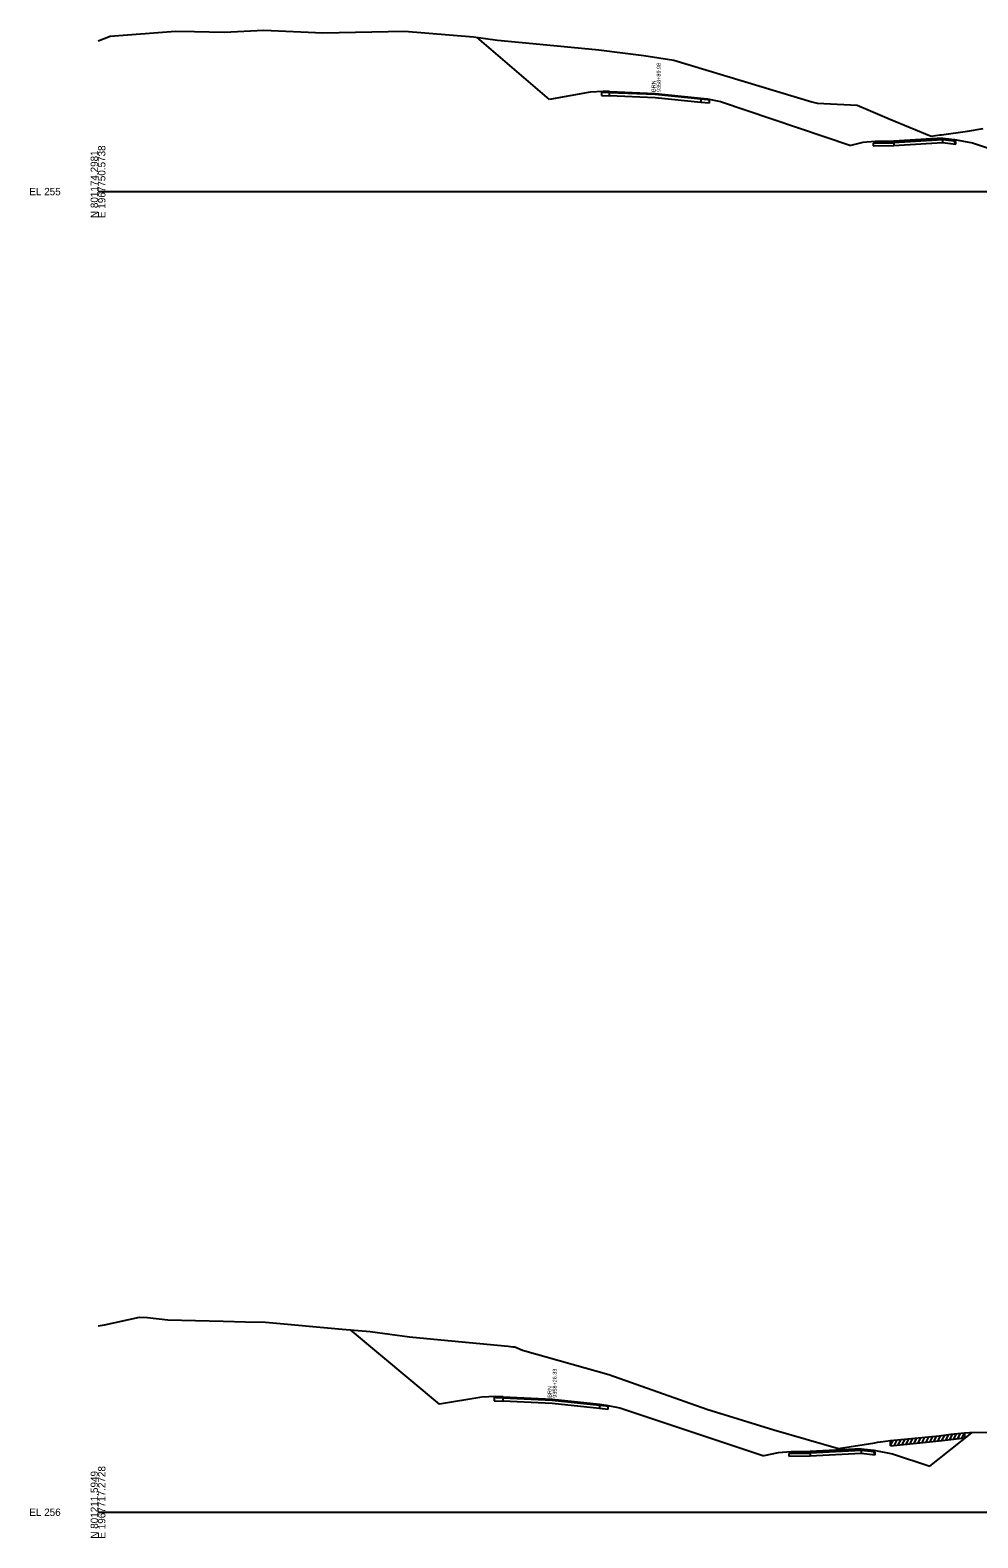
# Model space of a CAD drawing. Extents: x 1017 to 19997, y -1947 to 50737.
# Drawn here: x 13974 to 14333, y 2490 to 3061 of the extents above; entities that cross this region are included whole.
import ezdxf

# ---------------------------------------------------------------- set-up
doc = ezdxf.new("R2010")
doc.units = 0
for name, color, linetype in [('RD_GPK_XS_Cell', 7, 'Continuous'), ('RD_XS_Base', 7, 'Continuous'), ('RD_XS_ExGround', 7, 'Continuous'), ('RD_XS_ExPaveRet', 7, 'Continuous'), ('RD_XS_Greenside', 7, 'Continuous'), ('RD_XS_Pave', 7, 'Continuous'), ('RD_XS_PaveOvlay', 7, 'Continuous'), ('RD_XS_TieSlope', 7, 'Continuous'), ('RD_XS_TX_Notes', 7, 'Continuous')]:
    doc.layers.add(name, color=color, linetype=linetype)

msp = doc.modelspace()

# ---------------------------------------------------------------- linework, layer by layer
at = {"layer": 'RD_GPK_XS_Cell'}
for p, q in [((14000, 3000), (14600, 3000)), ((14000, 2500), (14600, 2500))]:
    msp.add_line(p, q, dxfattribs=at)
at = {"layer": 'RD_XS_Base'}
for points in [[(14190.63, 3037.66), (14190.63, 3036.33)], [(14193.71, 3037.54), (14190.63, 3037.66)], [(14193.71, 3037.54), (14211, 3036.85), (14228.28, 3035.07)], [(14193.71, 3036.2), (14193.71, 3037.54)], [(14190.63, 3036.33), (14193.71, 3036.2)], [(14228.28, 3033.76), (14211, 3035.51), (14193.71, 3036.2)], [(14228.28, 3035.07), (14228.28, 3033.76)], [(14228.28, 3035.07), (14230.75, 3034.82), (14231.37, 3034.76)], [(14231.37, 3033.42), (14228.28, 3033.76)], [(14231.37, 3034.76), (14231.37, 3033.42)], [(14319.66, 3019.63), (14319.66, 3018.63)], [(14324.82, 3018.01), (14324.25, 3019.08), (14319.66, 3019.63)], [(14324.82, 3019.01), (14324.25, 3019.08), (14319.66, 3019.63)], [(14301.3, 3018.44), (14294.27, 3018.32), (14293.44, 3018.3)], [(14293.44, 3018.3), (14293.44, 3017.3)], [(14293.44, 3017.3), (14301.3, 3017.44)], [(14301.3, 3017.44), (14319.66, 3018.63)], [(14301.3, 3018.44), (14301.3, 3017.44)], [(14319.66, 3018.63), (14324.82, 3018.01)], [(14324.82, 3018.01), (14324.82, 3019.01)], [(14150, 2543.52), (14150, 2542.19)], [(14153.33, 2543.36), (14150, 2543.52)], [(14150, 2542.19), (14153.33, 2542.02)], [(14153.33, 2543.36), (14171.9, 2542.47), (14189.82, 2540.54)], [(14153.33, 2542.02), (14153.33, 2543.36)], [(14189.82, 2539.23), (14171.9, 2541.13), (14153.33, 2542.02)], [(14189.82, 2540.54), (14189.82, 2539.23)], [(14189.82, 2540.54), (14192.38, 2540.27), (14193.03, 2540.2)], [(14193.03, 2540.2), (14193.03, 2538.87)], [(14193.03, 2538.87), (14189.82, 2539.23)], [(14288.97, 2523.41), (14288.97, 2522.41)], [(14294.27, 2521.76), (14293.68, 2522.84), (14288.97, 2523.41)], [(14294.27, 2522.76), (14293.68, 2522.84), (14288.97, 2523.41)], [(14269.65, 2522.35), (14262.37, 2522.28), (14261.52, 2522.27)], [(14261.52, 2522.27), (14261.52, 2521.27)], [(14261.52, 2521.27), (14269.65, 2521.35)], [(14269.65, 2521.35), (14288.97, 2522.41)], [(14269.65, 2522.35), (14269.65, 2521.35)], [(14288.97, 2522.41), (14294.27, 2521.76)], [(14294.27, 2521.76), (14294.27, 2522.76)]]:
    msp.add_lwpolyline(points, dxfattribs=at)
at = {"layer": 'RD_XS_ExGround'}
for points in [[(14000, 3057.03), (14004.57, 3058.82), (14029.3, 3060.76), (14036.48, 3060.64), (14047.73, 3060.33), (14062.72, 3061.12), (14085.15, 3060.1), (14116.05, 3060.71), (14142.13, 3058.58), (14151.25, 3057.36), (14169.89, 3055.58), (14189.65, 3053.69), (14198.53, 3052.49), (14206.66, 3051.47), (14217.95, 3049.7), (14270.25, 3033.97), (14272.29, 3033.46), (14287.44, 3032.69), (14291.61, 3030.91), (14299.48, 3027.61), (14315.49, 3020.99), (14318.76, 3021.45), (14319.29, 3021.54), (14329.19, 3022.91), (14335.08, 3023.84)], [(14000, 2570.62), (14002.4, 2570.96), (14015.71, 2573.92), (14018.68, 2573.77), (14026.37, 2572.88), (14047.44, 2572.4), (14055.86, 2572.15), (14063.37, 2571.97), (14092.48, 2569.27), (14102.98, 2568.41), (14117.96, 2566.41), (14129.85, 2565.28), (14155.3, 2562.85), (14157.04, 2562.65), (14157.8, 2562.61), (14160.71, 2561.32), (14193.39, 2552.12), (14230.56, 2539.08), (14255.88, 2531.26), (14280.33, 2524.15), (14294.16, 2526.34), (14295.13, 2526.49), (14296.29, 2526.7), (14300, 2527.2), (14318.5, 2528.99), (14322.94, 2529.5), (14328.08, 2530.12), (14329.96, 2530.13), (14342.19, 2530.3)]]:
    msp.add_lwpolyline(points, dxfattribs=at)
at = {"layer": 'RD_XS_ExPaveRet'}
for p, q in [((14315, 2526.65), (14316.05, 2528.75)), ((14316.5, 2526.79), (14317.55, 2528.9)), ((14318, 2526.94), (14319.06, 2529.05)), ((14319.5, 2527.1), (14320.56, 2529.22)), ((14321, 2527.28), (14322.06, 2529.4)), ((14322.5, 2527.45), (14323.56, 2529.57)), ((14324, 2527.63), (14325.07, 2529.76)), ((14325.5, 2527.81), (14326.57, 2529.94)), ((14327, 2527.99), (14328.07, 2530.12)), ((14328.08, 2530.12), (14328.08, 2528.12)), ((14300, 2525.2), (14301.05, 2527.3)), ((14300, 2525.2), (14300, 2527.2)), ((14300, 2525.2), (14318.5, 2526.99)), ((14301.5, 2525.34), (14302.55, 2527.44)), ((14303, 2525.49), (14304.05, 2527.59)), ((14304.5, 2525.63), (14305.55, 2527.73)), ((14306, 2525.78), (14307.05, 2527.88)), ((14307.5, 2525.92), (14308.55, 2528.03)), ((14309, 2526.07), (14310.05, 2528.17)), ((14310.5, 2526.21), (14311.55, 2528.32)), ((14312, 2526.36), (14313.05, 2528.46)), ((14313.5, 2526.5), (14314.55, 2528.61)), ((14318.5, 2526.99), (14322.94, 2527.5)), ((14322.94, 2527.5), (14328.08, 2528.12))]:
    msp.add_line(p, q, dxfattribs=at)
at = {"layer": 'RD_XS_Greenside'}
for points in [[(14186.29, 3037.68), (14170.93, 3034.83)], [(14191.24, 3037.96), (14186.29, 3037.68)], [(14230.75, 3035.14), (14235.69, 3034.15)], [(14235.69, 3034.15), (14284.96, 3017.5)], [(14324.25, 3019.71), (14331.13, 3018.42)], [(14289.55, 3018.56), (14284.96, 3017.5)], [(14294.27, 3018.95), (14289.55, 3018.56)], [(14331.13, 3018.42), (14344.9, 3013.75)], [(14145.33, 2543.59), (14129.34, 2540.89)], [(14150.66, 2543.81), (14145.33, 2543.59)], [(14192.38, 2540.59), (14197.51, 2539.57)], [(14197.51, 2539.57), (14252.04, 2521.36)], [(14293.68, 2523.47), (14300.75, 2522.13)], [(14257.51, 2522.55), (14252.04, 2521.36)], [(14262.37, 2522.92), (14257.51, 2522.55)], [(14300.75, 2522.13), (14314.9, 2517.39)]]:
    msp.add_lwpolyline(points, dxfattribs=at)
at = {"layer": 'RD_XS_Pave'}
for points in [[(14301.3, 3018.76), (14319.66, 3019.95)], [(14319.66, 3019.63), (14301.3, 3018.44)], [(14319.66, 3019.95), (14319.66, 3019.63)], [(14319.66, 3019.95), (14324.25, 3019.4)], [(14324.25, 3019.08), (14319.66, 3019.63)], [(14301.3, 3018.76), (14294.27, 3018.64)], [(14294.27, 3018.64), (14294.27, 3018.32)], [(14294.27, 3018.32), (14301.3, 3018.44)], [(14301.3, 3018.44), (14301.3, 3018.76)], [(14324.25, 3019.4), (14324.25, 3019.08)], [(14269.65, 2522.67), (14288.97, 2523.73)], [(14288.97, 2523.41), (14269.65, 2522.35)], [(14288.97, 2523.73), (14288.97, 2523.41)], [(14288.97, 2523.73), (14293.68, 2523.15)], [(14293.68, 2522.84), (14288.97, 2523.41)], [(14293.68, 2523.15), (14293.68, 2522.84)], [(14269.65, 2522.67), (14262.37, 2522.6)], [(14262.37, 2522.6), (14262.37, 2522.28)], [(14262.37, 2522.28), (14269.65, 2522.35)], [(14269.65, 2522.35), (14269.65, 2522.67)]]:
    msp.add_lwpolyline(points, dxfattribs=at)
at = {"layer": 'RD_XS_PaveOvlay'}
for points in [[(14191.24, 3037.96), (14191.24, 3037.64)], [(14193.71, 3037.85), (14191.24, 3037.96)], [(14191.24, 3037.64), (14193.71, 3037.54)], [(14193.71, 3037.85), (14211, 3037.16), (14228.28, 3035.39)], [(14193.71, 3037.54), (14193.71, 3037.85)], [(14228.28, 3035.39), (14228.28, 3035.07)], [(14228.28, 3035.39), (14230.75, 3035.14)], [(14230.75, 3034.82), (14228.28, 3035.07)], [(14230.75, 3035.14), (14230.75, 3034.82)], [(14319.66, 3020.26), (14301.3, 3019.07)], [(14319.66, 3019.95), (14319.66, 3020.26)], [(14319.66, 3020.26), (14324.25, 3019.71)], [(14324.25, 3019.71), (14324.25, 3019.4)], [(14301.3, 3019.07), (14294.27, 3018.95)], [(14294.27, 3018.95), (14294.27, 3018.64)], [(14301.3, 3019.07), (14301.3, 3018.76)], [(14150.66, 2543.81), (14150.66, 2543.49)], [(14153.33, 2543.67), (14150.66, 2543.81)], [(14150.66, 2543.49), (14153.33, 2543.36)], [(14153.33, 2543.67), (14171.9, 2542.78), (14189.82, 2540.86)], [(14153.33, 2543.36), (14153.33, 2543.67)], [(14189.82, 2540.86), (14189.82, 2540.54)], [(14189.82, 2540.86), (14192.38, 2540.59)], [(14192.38, 2540.27), (14189.82, 2540.54)], [(14192.38, 2540.59), (14192.38, 2540.27)], [(14288.97, 2524.05), (14269.65, 2522.99)], [(14288.97, 2523.73), (14288.97, 2524.05)], [(14288.97, 2524.05), (14293.68, 2523.47)], [(14293.68, 2523.47), (14293.68, 2523.15)], [(14269.65, 2522.99), (14262.37, 2522.92)], [(14262.37, 2522.92), (14262.37, 2522.6)], [(14269.65, 2522.99), (14269.65, 2522.67)]]:
    msp.add_lwpolyline(points, dxfattribs=at)
at = {"layer": 'RD_XS_TieSlope'}
for points in [[(14170.93, 3034.83), (14143.52, 3058.38)], [(14129.34, 2540.89), (14095.62, 2569.01)], [(14314.9, 2517.39), (14330.85, 2530.1)]]:
    msp.add_lwpolyline(points, dxfattribs=at)

# ---------------------------------------------------------------- texts
at = {"layer": 'RD_GPK_XS_Cell'}
for s, p in [('N 801174.2981', (14000, 2990)), ('E 1967750.5738', (14002.8, 2990)), ('E 1967717.2728', (14002.8, 2490)), ('N 801211.5949', (14000, 2490))]:
    msp.add_text(s, height=2.8, rotation=90, dxfattribs=at).set_placement(p)
for s, p in [('EL 255', (13974, 2998.6)), ('EL 256', (13974, 2498.6))]:
    msp.add_text(s, height=2.8, dxfattribs=at).set_placement(p)
at = {"layer": 'RD_XS_TX_Notes'}
for s, p in [(' 9358+89.98', (14213.03, 3037.14)), (' BRN', (14211.08, 3037.14)), (' 9358+26.33', (14173.67, 2542.78)), (' BRN', (14171.71, 2542.78))]:
    msp.add_text(s, height=1.5, rotation=90, dxfattribs=at).set_placement(p)

doc.saveas('drawing.dxf')
